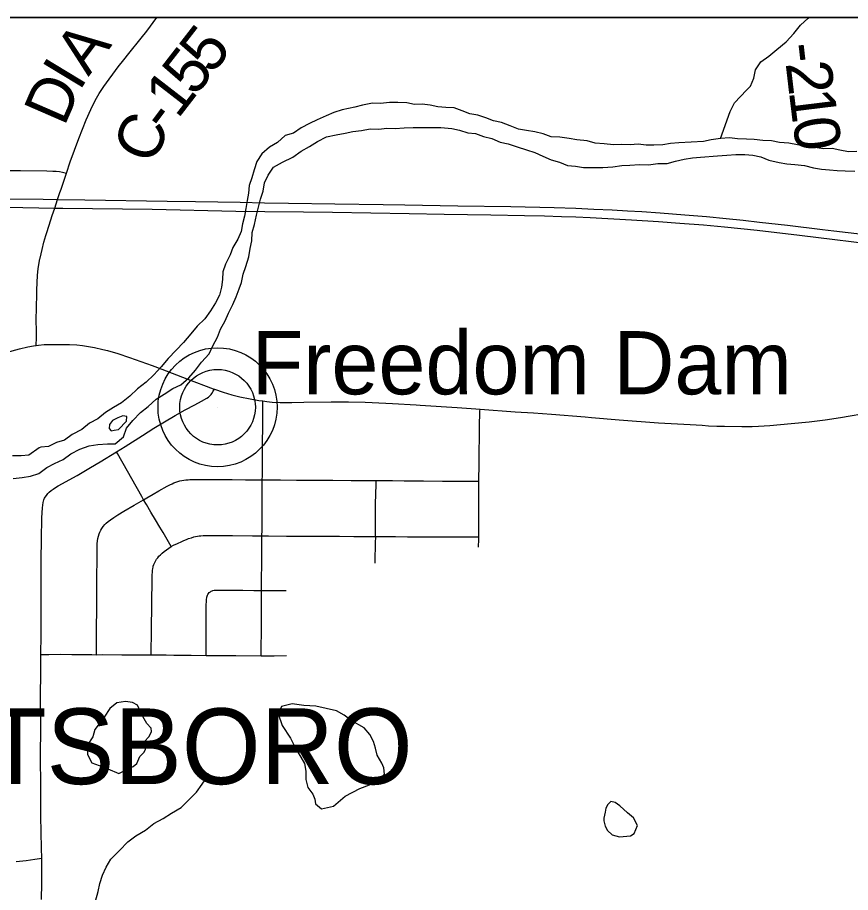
# Model space of a CAD drawing. Extents: x 0 to 34, y 0 to 22.
# Drawn here: x 5.497 to 6.537, y 19.806 to 20.9 of the extents above; entities that cross this region are included whole.
import ezdxf

# ---------------------------------------------------------------- set-up
doc = ezdxf.new("R2010")
doc.units = 0
for name, color, linetype in [('GM_X_Corporation', 7, 'Continuous'), ('GM_X_Corporation_Text', 7, 'Continuous'), ('GM_X_County_Road', 7, 'Continuous'), ('GM_X_County_Road_Text', 7, 'Continuous'), ('GM_X_Interstate_Route', 7, 'Continuous'), ('GM_X_Major_River', 7, 'Continuous'), ('GM_X_Minor_Lake', 7, 'Continuous'), ('GM_X_Minor_River', 7, 'Continuous'), ('GM_X_State_Route', 7, 'Continuous'), ('GM_X_Township_Road', 7, 'Continuous'), ('GM_X_Township_Road_Text', 7, 'Continuous'), ('GM_X_Unincorporated', 7, 'Continuous'), ('GM_X_Unincorporated_Location', 7, 'Continuous'), ('GM_X_Unincorporated_Text', 7, 'Continuous'), ('SH_Data', 7, 'Continuous')]:
    doc.layers.add(name, color=color, linetype=linetype)

msp = doc.modelspace()

# ---------------------------------------------------------------- linework, layer by layer
at = {"layer": 'GM_X_Corporation'}
msp.add_lwpolyline([(8.9, 20.9), (5.0198, 20.9)], dxfattribs=at)
at = {"layer": 'GM_X_County_Road'}
for points in [[(5.5578, 20.7054), (5.5625, 20.7196), (5.5733, 20.7488), (5.5825, 20.7719), (5.5882, 20.785), (5.5937, 20.7962), (5.5987, 20.8049), (5.6044, 20.8138), (5.6226, 20.8384), (5.6294, 20.8472), (5.6356, 20.855), (5.6512, 20.8743), (5.6581, 20.8831), (5.6709, 20.9)], [(5.5246, 20.5981), (5.5248, 20.5991), (5.5273, 20.6101), (5.5297, 20.6191), (5.5309, 20.6233), (5.5321, 20.6275), (5.5332, 20.6311), (5.5382, 20.6471), (5.5401, 20.6524), (5.5432, 20.6618), (5.5467, 20.6724), (5.5496, 20.6813), (5.551, 20.6854), (5.5578, 20.7054)], [(5.5201, 20.4901), (5.5202, 20.5), (5.5203, 20.5117), (5.5201, 20.5183), (5.5205, 20.5407), (5.5206, 20.5509), (5.5208, 20.5595), (5.5217, 20.5775), (5.5226, 20.5862), (5.5246, 20.5981)], [(5.409, 20.4516), (5.428, 20.4599), (5.4499, 20.469), (5.4633, 20.4741), (5.4791, 20.4798), (5.4901, 20.4834), (5.499, 20.4857), (5.5096, 20.4883), (5.5166, 20.4896), (5.5201, 20.4901)], [(5.5257, 20.1038), (5.5261, 20.1277), (5.5261, 20.1438), (5.5261, 20.1617), (5.5261, 20.1857), (5.5261, 20.205), (5.5263, 20.2217), (5.5266, 20.2478), (5.5272, 20.2746), (5.5279, 20.2871), (5.5282, 20.2902), (5.5287, 20.2937), (5.5291, 20.2955), (5.5297, 20.2972), (5.5303, 20.2989), (5.5312, 20.3004), (5.5327, 20.3026)], [(5.5271, 19.8491), (5.5268, 19.8615), (5.526, 19.9015), (5.5257, 19.9233), (5.5256, 19.9488), (5.5254, 19.9662), (5.5254, 19.9793), (5.5259, 20.0091), (5.5254, 20.0487), (5.5257, 20.0842), (5.5257, 20.1038)], [(5.5268, 19.7974), (5.5271, 19.8178), (5.5271, 19.8491)]]:
    msp.add_lwpolyline(points, dxfattribs=at)
at = {"layer": 'GM_X_Interstate_Route'}
for points in [[(5.4801, 20.6735), (5.5288, 20.6727), (5.5467, 20.6724), (5.5808, 20.6719), (5.6835, 20.6703), (5.7189, 20.6698), (5.7748, 20.669), (5.8052, 20.6685), (5.8352, 20.668), (5.8933, 20.6671), (5.9534, 20.6661), (5.9806, 20.6657), (6.047, 20.6647), (6.1131, 20.6636), (6.167, 20.6624), (6.1941, 20.6617), (6.2169, 20.6606), (6.2395, 20.6595), (6.259, 20.6583), (6.2766, 20.6573), (6.2995, 20.6558), (6.3306, 20.6534), (6.3575, 20.6511), (6.3819, 20.6488), (6.4034, 20.6466), (6.4236, 20.6443), (6.4586, 20.6403), (6.5024, 20.635), (6.5164, 20.6334), (6.5347, 20.6313), (6.5915, 20.6245)], [(5.4637, 20.6629), (5.5031, 20.6623), (5.5432, 20.6618), (5.5533, 20.6616), (5.6648, 20.6602), (5.7695, 20.6579), (5.8058, 20.6575), (5.8541, 20.6569), (5.8904, 20.6565), (5.9858, 20.6549), (6.0297, 20.6541), (6.0882, 20.6532), (6.1302, 20.6525), (6.1553, 20.6519), (6.1765, 20.6512), (6.1941, 20.6507), (6.2121, 20.65), (6.264, 20.6471), (6.2976, 20.6451), (6.324, 20.6429), (6.3536, 20.6407), (6.38, 20.6385), (6.421, 20.6342), (6.4738, 20.6277), (6.5177, 20.6226), (6.579, 20.6149)]]:
    msp.add_lwpolyline(points, dxfattribs=at)
at = {"layer": 'GM_X_Major_River'}
msp.add_line((5.6228, 20.385), (5.6329, 20.3953), dxfattribs=at)
for points in [[(6.0618, 20.7794), (6.0524, 20.7835), (6.0421, 20.7869), (6.0319, 20.7876), (6.022, 20.7882), (6.0122, 20.7904), (6.0023, 20.7915), (5.9925, 20.7914), (5.983, 20.7933), (5.972, 20.7936), (5.9614, 20.7938), (5.9501, 20.7926), (5.9402, 20.7929), (5.9278, 20.7906), (5.918, 20.7878), (5.9025, 20.7847), (5.8919, 20.7812), (5.8821, 20.7769), (5.8711, 20.7719), (5.8613, 20.7673), (5.8512, 20.7619), (5.8414, 20.7554), (5.8312, 20.7523), (5.8214, 20.7438), (5.8116, 20.7377), (5.8018, 20.7297), (5.7958, 20.7198), (5.7925, 20.7095), (5.7896, 20.6996), (5.7859, 20.6901), (5.7852, 20.6806), (5.7834, 20.6711), (5.7819, 20.6612), (5.7801, 20.6517), (5.7779, 20.6422), (5.7761, 20.6324), (5.772, 20.6229), (5.7656, 20.6126), (5.7623, 20.6031), (5.7567, 20.5916), (5.753, 20.5821), (5.7527, 20.5723), (5.7516, 20.5628), (5.7491, 20.5529), (5.7442, 20.5434), (5.7379, 20.5331), (5.7307, 20.5235), (5.721, 20.514), (5.7131, 20.5044), (5.7041, 20.4937), (5.6947, 20.4842), (5.685, 20.4735), (5.6763, 20.4632), (5.6669, 20.4533), (5.6572, 20.4441), (5.6466, 20.4357), (5.6369, 20.4265), (5.6267, 20.4184), (5.6165, 20.4123), (5.6067, 20.4061), (5.597, 20.3981), (5.5868, 20.3927), (5.577, 20.3851), (5.5649, 20.3789), (5.5552, 20.3716), (5.5453, 20.3689), (5.5355, 20.3635), (5.5257, 20.3627), (5.5238, 20.3619)], [(6.5452, 20.7323), (6.5349, 20.7319), (6.5243, 20.734), (6.5145, 20.7362), (6.5035, 20.7358), (6.4929, 20.7376), (6.4815, 20.7386), (6.4713, 20.7408), (6.4603, 20.7427), (6.4489, 20.7437), (6.4387, 20.7459), (6.4277, 20.7462), (6.4171, 20.7473), (6.4073, 20.7479), (6.3963, 20.7482), (6.3861, 20.7497), (6.3751, 20.7488), (6.3634, 20.7469), (6.3536, 20.7449), (6.3229, 20.7435), (6.3127, 20.7423), (6.3029, 20.7407), (6.2919, 20.7402), (6.2821, 20.7405), (6.2722, 20.7416), (6.262, 20.7408), (6.2518, 20.7411), (6.2415, 20.741), (6.2298, 20.742), (6.2184, 20.7431), (6.2086, 20.7457), (6.1953, 20.7471), (6.1858, 20.7489), (6.1741, 20.7503), (6.1635, 20.751), (6.1536, 20.7547), (6.143, 20.7569), (6.1324, 20.7587), (6.1226, 20.7602), (6.1123, 20.7647), (6.1013, 20.7687), (6.0914, 20.7709), (6.0819, 20.7747), (6.0717, 20.778), (6.0618, 20.7794)], [(5.7735, 20.5607), (5.7766, 20.5687), (5.7788, 20.579), (5.7821, 20.5889), (5.7857, 20.6007), (5.7875, 20.6114), (5.7893, 20.6209), (5.7899, 20.6311), (5.7929, 20.6414), (5.7954, 20.6528), (5.7976, 20.6627), (5.8001, 20.673), (5.8034, 20.6829), (5.8052, 20.6932), (5.81, 20.7031), (5.8167, 20.7127), (5.8276, 20.7193), (5.8408, 20.7255), (5.8509, 20.7329), (5.8615, 20.7387), (5.8716, 20.7449), (5.8829, 20.7507), (5.8946, 20.7535), (5.906, 20.7555), (5.9158, 20.7575), (5.9264, 20.7588), (5.9374, 20.7608), (5.948, 20.7606), (5.9582, 20.7615), (5.9684, 20.7612), (5.9798, 20.7621), (5.9911, 20.7626), (6.0032, 20.7624), (6.0256, 20.7626), (6.0392, 20.7613), (6.0487, 20.7591), (6.0594, 20.7558), (6.0688, 20.7548), (6.0787, 20.7511), (6.0894, 20.7486), (6.0996, 20.7441), (6.1095, 20.742), (6.1209, 20.7383), (6.1327, 20.7346), (6.143, 20.7313), (6.1532, 20.7265), (6.1635, 20.7221), (6.1738, 20.7192), (6.1837, 20.7151), (6.1939, 20.7141), (6.2038, 20.7123), (6.228, 20.7126), (6.2405, 20.7135), (6.2518, 20.7148), (6.2617, 20.7153), (6.2738, 20.7161), (6.2852, 20.7159), (6.2969, 20.7176), (6.3083, 20.7173), (6.3188, 20.7205), (6.3298, 20.7229), (6.34, 20.7245), (6.3502, 20.7254), (6.3714, 20.7272), (6.3831, 20.7277), (6.3941, 20.7289), (6.4055, 20.7287), (6.4153, 20.7281), (6.4256, 20.7259), (6.4355, 20.7218), (6.4484, 20.7186), (6.4579, 20.7172), (6.4677, 20.7161), (6.4799, 20.7148), (6.4912, 20.7122), (6.5011, 20.7104), (6.511, 20.7094), (6.5208, 20.7088), (6.5307, 20.7085), (6.5428, 20.7079)], [(5.4913, 20.3238), (5.5026, 20.3251), (5.5128, 20.3267), (5.5234, 20.3299), (5.5332, 20.3376), (5.543, 20.3426), (5.5535, 20.3473), (5.5633, 20.3546), (5.5746, 20.3605), (5.5863, 20.3644), (5.5969, 20.366), (5.609, 20.3669), (5.6188, 20.3671), (5.6289, 20.3759), (5.633, 20.3866), (5.6408, 20.3962), (5.6502, 20.4062), (5.66, 20.4139), (5.6701, 20.4227), (5.6799, 20.4293), (5.6908, 20.4363), (5.7009, 20.4409), (5.7107, 20.4494), (5.7189, 20.459), (5.7264, 20.469), (5.7361, 20.4797), (5.7409, 20.4896), (5.7465, 20.5003), (5.7502, 20.5103), (5.7561, 20.5206), (5.7602, 20.5305), (5.7657, 20.5412), (5.7698, 20.5507), (5.7735, 20.5607)], [(5.6329, 20.3953), (5.6333, 20.4014), (5.6284, 20.4021), (5.6219, 20.3994), (5.6155, 20.3963), (5.6114, 20.3914), (5.6111, 20.3861), (5.6137, 20.3834), (5.6175, 20.3842), (5.6228, 20.385)], [(5.5238, 20.3619), (5.511, 20.3527), (5.5012, 20.3522), (5.4906, 20.3521)]]:
    msp.add_lwpolyline(points, dxfattribs=at)
at = {"layer": 'GM_X_Minor_Lake'}
for p, q in [((5.6051, 20.0253), (5.5931, 20.01)), ((5.9296, 20.0119), (5.9136, 20.0212)), ((6.2309, 19.9064), (6.2294, 19.899))]:
    msp.add_line(p, q, dxfattribs=at)
for points in [[(5.5931, 20.01), (5.5906, 20.0009), (5.5838, 19.9899), (5.5843, 19.9785), (5.5897, 19.9683), (5.5988, 19.9649), (5.6094, 19.9609), (5.6231, 19.9549), (5.6412, 19.9638), (5.6457, 19.9676), (5.6494, 19.976), (5.6543, 19.9813), (5.6565, 19.9847), (5.6569, 19.9889), (5.655, 19.9946), (5.661, 20.0011), (5.6639, 20.0072), (5.6635, 20.0117), (5.6582, 20.0174), (5.6517, 20.0291), (5.6467, 20.0404), (5.6402, 20.0438), (5.6315, 20.0449), (5.6209, 20.0433), (5.6119, 20.036), (5.6051, 20.0253)], [(5.9136, 20.0212), (5.9049, 20.028), (5.8954, 20.0332), (5.8692, 20.0391), (5.8544, 20.0401), (5.84, 20.0419), (5.8264, 20.0388), (5.8224, 20.0296), (5.8274, 20.0149), (5.8377, 19.999), (5.8439, 19.9865), (5.8508, 19.9752), (5.8554, 19.9673), (5.857, 19.9578), (5.8571, 19.9472), (5.8594, 19.9374), (5.8655, 19.9291), (5.8682, 19.923), (5.869, 19.9169), (5.8766, 19.9109), (5.8914, 19.9141), (5.906, 19.9267), (5.9245, 19.9363), (5.9366, 19.9406), (5.9498, 19.9464), (5.955, 19.954), (5.9542, 19.962), (5.9519, 19.968), (5.9461, 19.9778), (5.9438, 19.9866), (5.9415, 19.9949), (5.9369, 20.0036), (5.9296, 20.0119)], [(6.2294, 19.899), (6.2291, 19.8958), (6.2311, 19.889), (6.2338, 19.8837), (6.2395, 19.8784), (6.249, 19.8758), (6.2626, 19.8771), (6.2671, 19.8798), (6.2712, 19.8901), (6.2662, 19.8995), (6.2586, 19.9059), (6.2494, 19.9145), (6.2433, 19.9187), (6.238, 19.9198), (6.2343, 19.9163), (6.2316, 19.9117), (6.2309, 19.9064)]]:
    msp.add_lwpolyline(points, dxfattribs=at)
at = {"layer": 'GM_X_Minor_River'}
for points in [[(6.4075, 20.809), (6.4123, 20.814), (6.4168, 20.8242), (6.4186, 20.8345), (6.4254, 20.8444), (6.4352, 20.8517), (6.4454, 20.8601), (6.4571, 20.8696), (6.4666, 20.8799), (6.4749, 20.8906), (6.4847, 20.899), (6.4857, 20.9)], [(6.375, 20.7488), (6.3869, 20.7823), (6.3926, 20.7932), (6.4075, 20.809)], [(5.5698, 19.744), (5.5728, 19.7542), (5.5769, 19.7653), (5.5825, 19.7748), (5.5892, 19.7858), (5.594, 19.7954), (5.5974, 19.8075), (5.5995, 19.8174), (5.6029, 19.8277), (5.6073, 19.8379), (5.6133, 19.8479), (5.6242, 19.8586), (5.6343, 19.8696), (5.6445, 19.8769), (5.6566, 19.8842), (5.6671, 19.8926), (5.6788, 19.8988), (5.6889, 19.9053), (5.701, 19.9122), (5.7202, 19.9317), (5.7273, 19.9417), (5.734, 19.9512), (5.7351, 19.9554)]]:
    msp.add_lwpolyline(points, dxfattribs=at)
at = {"layer": 'GM_X_State_Route'}
for points in [[(5.409, 20.4516), (5.428, 20.4599), (5.4499, 20.469), (5.4633, 20.4741), (5.4791, 20.4798), (5.4901, 20.4834), (5.499, 20.4857), (5.5096, 20.4883), (5.5166, 20.4896), (5.5201, 20.4901)], [(5.5201, 20.4901), (5.5227, 20.4905), (5.5301, 20.491), (5.5383, 20.4913), (5.5513, 20.4914), (5.5615, 20.4913), (5.5708, 20.4908), (5.578, 20.4899), (5.5928, 20.4874), (5.6031, 20.4851), (5.6092, 20.4836), (5.6218, 20.48), (5.6366, 20.4751), (5.6647, 20.465), (5.6769, 20.4604), (5.7082, 20.4483), (5.7413, 20.4357), (5.7426, 20.4353), (5.7536, 20.4315), (5.7643, 20.4283), (5.7745, 20.4258), (5.7872, 20.4231), (5.7982, 20.4212), (5.8032, 20.4206), (5.8081, 20.42), (5.8148, 20.4193), (5.8247, 20.4188), (5.8396, 20.4187), (5.8545, 20.419), (5.8887, 20.4194), (5.8943, 20.4194), (5.9104, 20.4194), (5.931, 20.4191), (5.9397, 20.4188), (5.9651, 20.4176), (5.9949, 20.4158)], [(6.214, 20.3999), (6.2483, 20.397), (6.2975, 20.3934), (6.3135, 20.3924), (6.337, 20.391), (6.3519, 20.3902), (6.3599, 20.3897), (6.3705, 20.3893), (6.3798, 20.389), (6.4015, 20.3887), (6.4145, 20.3888), (6.4226, 20.389), (6.4368, 20.39), (6.4634, 20.3924), (6.4856, 20.3945), (6.5059, 20.3972), (6.525, 20.4001), (6.5636, 20.4067), (6.6114, 20.4149), (6.6807, 20.4272)], [(5.9949, 20.4158), (5.9999, 20.4155), (6.0458, 20.4123), (6.0693, 20.4107), (6.0746, 20.4103)], [(6.0746, 20.4103), (6.1183, 20.4071), (6.1413, 20.4056), (6.164, 20.404), (6.2059, 20.4006), (6.214, 20.3999)]]:
    msp.add_lwpolyline(points, dxfattribs=at)
at = {"layer": 'GM_X_Township_Road'}
for points in [[(5.2688, 20.7119), (5.2859, 20.7116), (5.3133, 20.7112), (5.3395, 20.7108), (5.3685, 20.7103), (5.3953, 20.7099), (5.4341, 20.7094), (5.4706, 20.7089), (5.5004, 20.7086), (5.5332, 20.7082), (5.5407, 20.7081), (5.545, 20.7078), (5.5493, 20.7073), (5.5529, 20.7067), (5.5578, 20.7054)], [(5.6202, 20.3572), (5.6312, 20.3639), (5.6528, 20.3775), (5.667, 20.3865), (5.6802, 20.3947), (5.6936, 20.4025), (5.7061, 20.4094), (5.7182, 20.4159), (5.7264, 20.4202), (5.7331, 20.424), (5.7351, 20.4253), (5.737, 20.427), (5.7385, 20.4288), (5.7394, 20.43), (5.7412, 20.4329), (5.7426, 20.4353)], [(5.8025, 20.322), (5.8026, 20.3269), (5.8027, 20.3461), (5.8029, 20.3688), (5.803, 20.3883), (5.8031, 20.4033), (5.8032, 20.4184), (5.8032, 20.4206)], [(6.0732, 20.3202), (6.0733, 20.3426), (6.0734, 20.3539), (6.0738, 20.3785), (6.0739, 20.3901), (6.074, 20.396), (6.0741, 20.4001), (6.0743, 20.4042), (6.0745, 20.4078), (6.0746, 20.4103)], [(5.5327, 20.3026), (5.5344, 20.3048), (5.5364, 20.3066), (5.5389, 20.3085), (5.5412, 20.3103), (5.5442, 20.3124), (5.5475, 20.3145), (5.5712, 20.3276), (5.5877, 20.3373), (5.6, 20.3447), (5.6202, 20.3572)], [(5.6542, 20.2972), (5.652, 20.301), (5.6215, 20.355), (5.6202, 20.3572)], [(5.6542, 20.2972), (5.6581, 20.2995), (5.666, 20.3041), (5.6732, 20.3082), (5.6838, 20.3141), (5.6868, 20.3157), (5.6898, 20.3171), (5.6921, 20.3181), (5.6946, 20.3191), (5.697, 20.3199), (5.6996, 20.3206), (5.7021, 20.3212), (5.7045, 20.3216), (5.7068, 20.3219), (5.7097, 20.3222), (5.712, 20.3223), (5.7143, 20.3224), (5.7176, 20.3225), (5.722, 20.3225), (5.7303, 20.3225), (5.7411, 20.3225), (5.7514, 20.3225), (5.765, 20.3224), (5.7814, 20.3222), (5.7967, 20.3221), (5.8025, 20.322)], [(5.8021, 20.252), (5.8022, 20.2593), (5.8023, 20.2826), (5.8025, 20.3078), (5.8025, 20.322)], [(5.8025, 20.322), (5.8095, 20.322), (5.8252, 20.3219), (5.8454, 20.3218), (5.8656, 20.3216), (5.8907, 20.3215), (5.9134, 20.3213), (5.9267, 20.3212), (5.9405, 20.3211), (5.9448, 20.3211)], [(5.9439, 20.251), (5.944, 20.2608), (5.944, 20.2711), (5.9441, 20.2826), (5.9441, 20.2949), (5.9443, 20.301), (5.9444, 20.3054), (5.9446, 20.3151), (5.9447, 20.32), (5.9448, 20.3211)], [(5.9448, 20.3211), (5.9509, 20.3211), (5.965, 20.321), (5.9796, 20.3209), (6.0038, 20.3207), (6.0276, 20.3205), (6.0577, 20.3203), (6.072, 20.3202), (6.0732, 20.3202)], [(6.0729, 20.2506), (6.073, 20.259), (6.073, 20.2701), (6.0731, 20.286), (6.0732, 20.3123), (6.0732, 20.3202)], [(5.5952, 20.1034), (5.5952, 20.1059), (5.5953, 20.1217), (5.5955, 20.1382), (5.5957, 20.1587), (5.5959, 20.1862), (5.5959, 20.202), (5.596, 20.2212), (5.596, 20.2325), (5.5961, 20.2385), (5.5961, 20.2421), (5.5964, 20.2457), (5.5969, 20.2486), (5.5977, 20.2517), (5.5986, 20.2545), (5.5995, 20.2568), (5.6006, 20.2589), (5.6021, 20.2613), (5.6038, 20.2638), (5.6057, 20.2661), (5.6076, 20.2679), (5.6101, 20.2701), (5.6127, 20.2722), (5.6168, 20.2751), (5.6221, 20.2784), (5.6293, 20.2827), (5.6422, 20.2902), (5.6542, 20.2972)], [(5.6886, 20.2388), (5.6853, 20.2446), (5.6785, 20.2563), (5.6746, 20.2628), (5.6691, 20.2721), (5.6634, 20.2816), (5.6577, 20.2913), (5.6542, 20.2972)], [(5.6886, 20.2388), (5.6917, 20.2404), (5.6965, 20.2426), (5.702, 20.2451), (5.7046, 20.2462), (5.7077, 20.2475), (5.7104, 20.2486), (5.7139, 20.2497), (5.717, 20.2508), (5.7191, 20.2512), (5.7215, 20.2517), (5.7235, 20.252), (5.7256, 20.2522), (5.7288, 20.2524), (5.7316, 20.2526), (5.7346, 20.2526), (5.7402, 20.2525), (5.7502, 20.2524), (5.7653, 20.2523), (5.7904, 20.2521), (5.8021, 20.252)], [(5.8017, 20.1835), (5.8017, 20.1903), (5.8019, 20.2244), (5.802, 20.2415), (5.8021, 20.252)], [(5.8021, 20.252), (5.8102, 20.2519), (5.8328, 20.2517), (5.8509, 20.2516), (5.8694, 20.2515), (5.8833, 20.2514), (5.899, 20.2514), (5.9169, 20.2512), (5.9391, 20.251), (5.9439, 20.251)], [(5.9434, 20.218), (5.9436, 20.2252), (5.9438, 20.2379), (5.9438, 20.2446), (5.9442, 20.2496), (5.9439, 20.251)], [(5.9439, 20.251), (5.949, 20.251), (5.956, 20.251), (5.9688, 20.251), (5.9839, 20.2509), (6.004, 20.2509), (6.0202, 20.2508), (6.044, 20.2508), (6.0612, 20.2507), (6.0717, 20.2507), (6.0729, 20.2506)], [(6.0727, 20.2378), (6.0729, 20.2477), (6.0729, 20.2506)], [(5.6635, 20.1031), (5.6637, 20.1124), (5.664, 20.1259), (5.6641, 20.1372), (5.6644, 20.1639), (5.6645, 20.1762), (5.6647, 20.1891), (5.6649, 20.1973), (5.665, 20.2008), (5.6651, 20.2038), (5.6653, 20.2063), (5.6654, 20.2086), (5.6657, 20.2111), (5.666, 20.2128), (5.6663, 20.2141), (5.6669, 20.216), (5.6677, 20.218), (5.6689, 20.2203), (5.6705, 20.2227), (5.6718, 20.2244), (5.6734, 20.2264), (5.6754, 20.2284), (5.6774, 20.2303), (5.68, 20.2325), (5.6828, 20.2347), (5.6856, 20.2367), (5.6886, 20.2388)], [(5.7323, 20.1025), (5.7323, 20.1188), (5.7324, 20.1423), (5.7325, 20.1637), (5.7325, 20.1665), (5.7326, 20.169), (5.7327, 20.1713), (5.7329, 20.173), (5.7331, 20.1744), (5.7333, 20.1753), (5.7336, 20.1766), (5.734, 20.1778), (5.7345, 20.1787), (5.7353, 20.1799), (5.7363, 20.181), (5.7377, 20.1821), (5.7388, 20.1829), (5.7399, 20.1834), (5.7409, 20.1838), (5.7422, 20.1841), (5.7435, 20.1842), (5.7449, 20.1843), (5.7468, 20.1843), (5.7523, 20.1843), (5.7781, 20.1839), (5.7919, 20.1837), (5.8017, 20.1835)], [(5.8011, 20.102), (5.8012, 20.1092), (5.8012, 20.1172), (5.8013, 20.128), (5.8015, 20.1425), (5.8016, 20.1599), (5.8016, 20.1735), (5.8017, 20.1835)], [(5.8017, 20.1835), (5.8077, 20.1835), (5.8174, 20.1835), (5.8287, 20.1835), (5.8323, 20.1835)], [(5.5257, 20.1038), (5.5357, 20.1038), (5.5505, 20.1039), (5.5647, 20.1038), (5.5721, 20.1035), (5.5894, 20.1035), (5.5952, 20.1034)], [(5.5952, 20.1034), (5.6029, 20.1035), (5.627, 20.1033), (5.6345, 20.1032), (5.6525, 20.1031), (5.6587, 20.1031), (5.6635, 20.1031)], [(5.6635, 20.1031), (5.6655, 20.1031), (5.6822, 20.1031), (5.6921, 20.103), (5.7001, 20.1029), (5.7137, 20.1027), (5.7323, 20.1025)], [(5.7323, 20.1025), (5.7411, 20.1024), (5.7572, 20.1024), (5.767, 20.1023), (5.7694, 20.1023), (5.8011, 20.102)], [(5.8011, 20.102), (5.8066, 20.102), (5.8172, 20.1019), (5.8327, 20.1025)], [(5.4951, 19.845), (5.5075, 19.8462), (5.5185, 19.8478), (5.5271, 19.8491)]]:
    msp.add_lwpolyline(points, dxfattribs=at)
at = {"layer": 'GM_X_Unincorporated'}
for radius in [0.0744, 0.0472]:
    msp.add_circle((5.7466, 20.4128), radius, dxfattribs=at)
at = {"layer": 'GM_X_Unincorporated_Location'}
msp.add_line((5.7466, 20.4128), (5.7466, 20.4128), dxfattribs=at)
at = {"layer": 'SH_Data'}
msp.add_line((2.1, 20.9), (8.9, 20.9), dxfattribs=at)

# ---------------------------------------------------------------- texts
at = {"layer": 'GM_X_Corporation_Text'}
msp.add_text('STREETSBORO', height=0.094697, rotation=0, dxfattribs=at).set_placement((5.0335, 19.9416))
at = {"layer": 'GM_X_County_Road_Text'}
for s, rotation, p in [('A', 53.3261, (5.5853, 20.8255)), ('5', 52.1497, (5.7396, 20.8275)), ('5', 52.1944, (5.7182, 20.7998)), ('I', 58.7832, (5.574, 20.8067)), ('1', 52.2797, (5.6968, 20.7722)), ('D', 66.4551, (5.555, 20.7627)), ('-', 53.0911, (5.6829, 20.7537)), ('C', 66.0942, (5.6657, 20.7139))]:
    msp.add_text(s, height=0.0568, rotation=rotation, dxfattribs=at).set_placement(p)
at = {"layer": 'GM_X_Township_Road_Text'}
for s, rotation, p in [('-', 276.5622, (6.4536, 20.8663)), ('2', 276.6648, (6.4563, 20.843)), ('1', 276.9817, (6.4604, 20.8079)), ('0', 277.9366, (6.4648, 20.7721))]:
    msp.add_text(s, height=0.0568, rotation=rotation, dxfattribs=at).set_placement(p)
at = {"layer": 'GM_X_Unincorporated_Text'}
msp.add_text('Freedom Dam', height=0.078977, rotation=0, dxfattribs=at).set_placement((5.7892, 20.4289))

doc.saveas('drawing.dxf')
